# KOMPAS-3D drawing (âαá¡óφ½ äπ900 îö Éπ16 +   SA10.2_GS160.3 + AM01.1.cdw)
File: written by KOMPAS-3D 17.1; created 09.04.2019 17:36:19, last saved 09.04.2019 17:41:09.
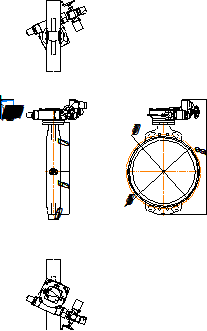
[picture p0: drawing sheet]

Sheet 1: A4, portrait

Title block, sheet 1: name: Гранвэл Ду900 МФ Ру16 + / SA10.2_GS160.3 + AM01.1; material: Внимание! Данный продукт является объектом авторского права ООО «Торговый Дом АДЛ». / Запрещается изменение, копирование, распространение / (в том числе путем копирования на другие сайты и ресурсы в Интернете) / или любое иное использование информации и объектов без предварительного / согласия правообладателя (ООО «Торговый Дом АДЛ»).; mass: 1330,47; sheets: 1; organisation: ООО "Торговый дом АДЛ"; sheet format: A4

Views: Вид 1, Проекционный вид 2, Проекционный вид 3, Проекционный вид 4
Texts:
  user
Dimensions and other numbers on the sheet: 770; 675; 150; 1812,8; 1170; 1115,76; 1:1; 1; 1330,47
